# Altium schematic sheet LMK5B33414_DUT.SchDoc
size C; Date: Not shown in title block; ApprovedBy: Not shown in title block; CheckedBy: Not shown in title block; Author: Not shown in title block; CompanyName: Not shown in title block; Engineer: Not shown in title block; Organization: Not shown in title block; Address1: Not shown in title block; Address2: Not shown in title block; Address3: Not shown in title block; Address4: Not shown in title block; DocumentNumber: 2; Revision: Use project parameter SCH_Rev; SheetNumber: 2; SheetTotal: 3; PageSetup: Record=PageOptions¦CenterHorizontal=True¦CenterVertical=True¦PrintScale=1.00¦XCorrection=1.00¦YCorrection=1.00¦PrintKind=0¦BorderSize=5000000¦LeftOffset=0¦BottomOffset=0¦Orientation=2¦PaperLength=1000¦PaperWidth=1000¦Scale=100¦PaperSource=15¦PrintQuality=600¦MediaType=1¦DitherType=10¦PaperKind=Letter¦PrintScaleMode=1
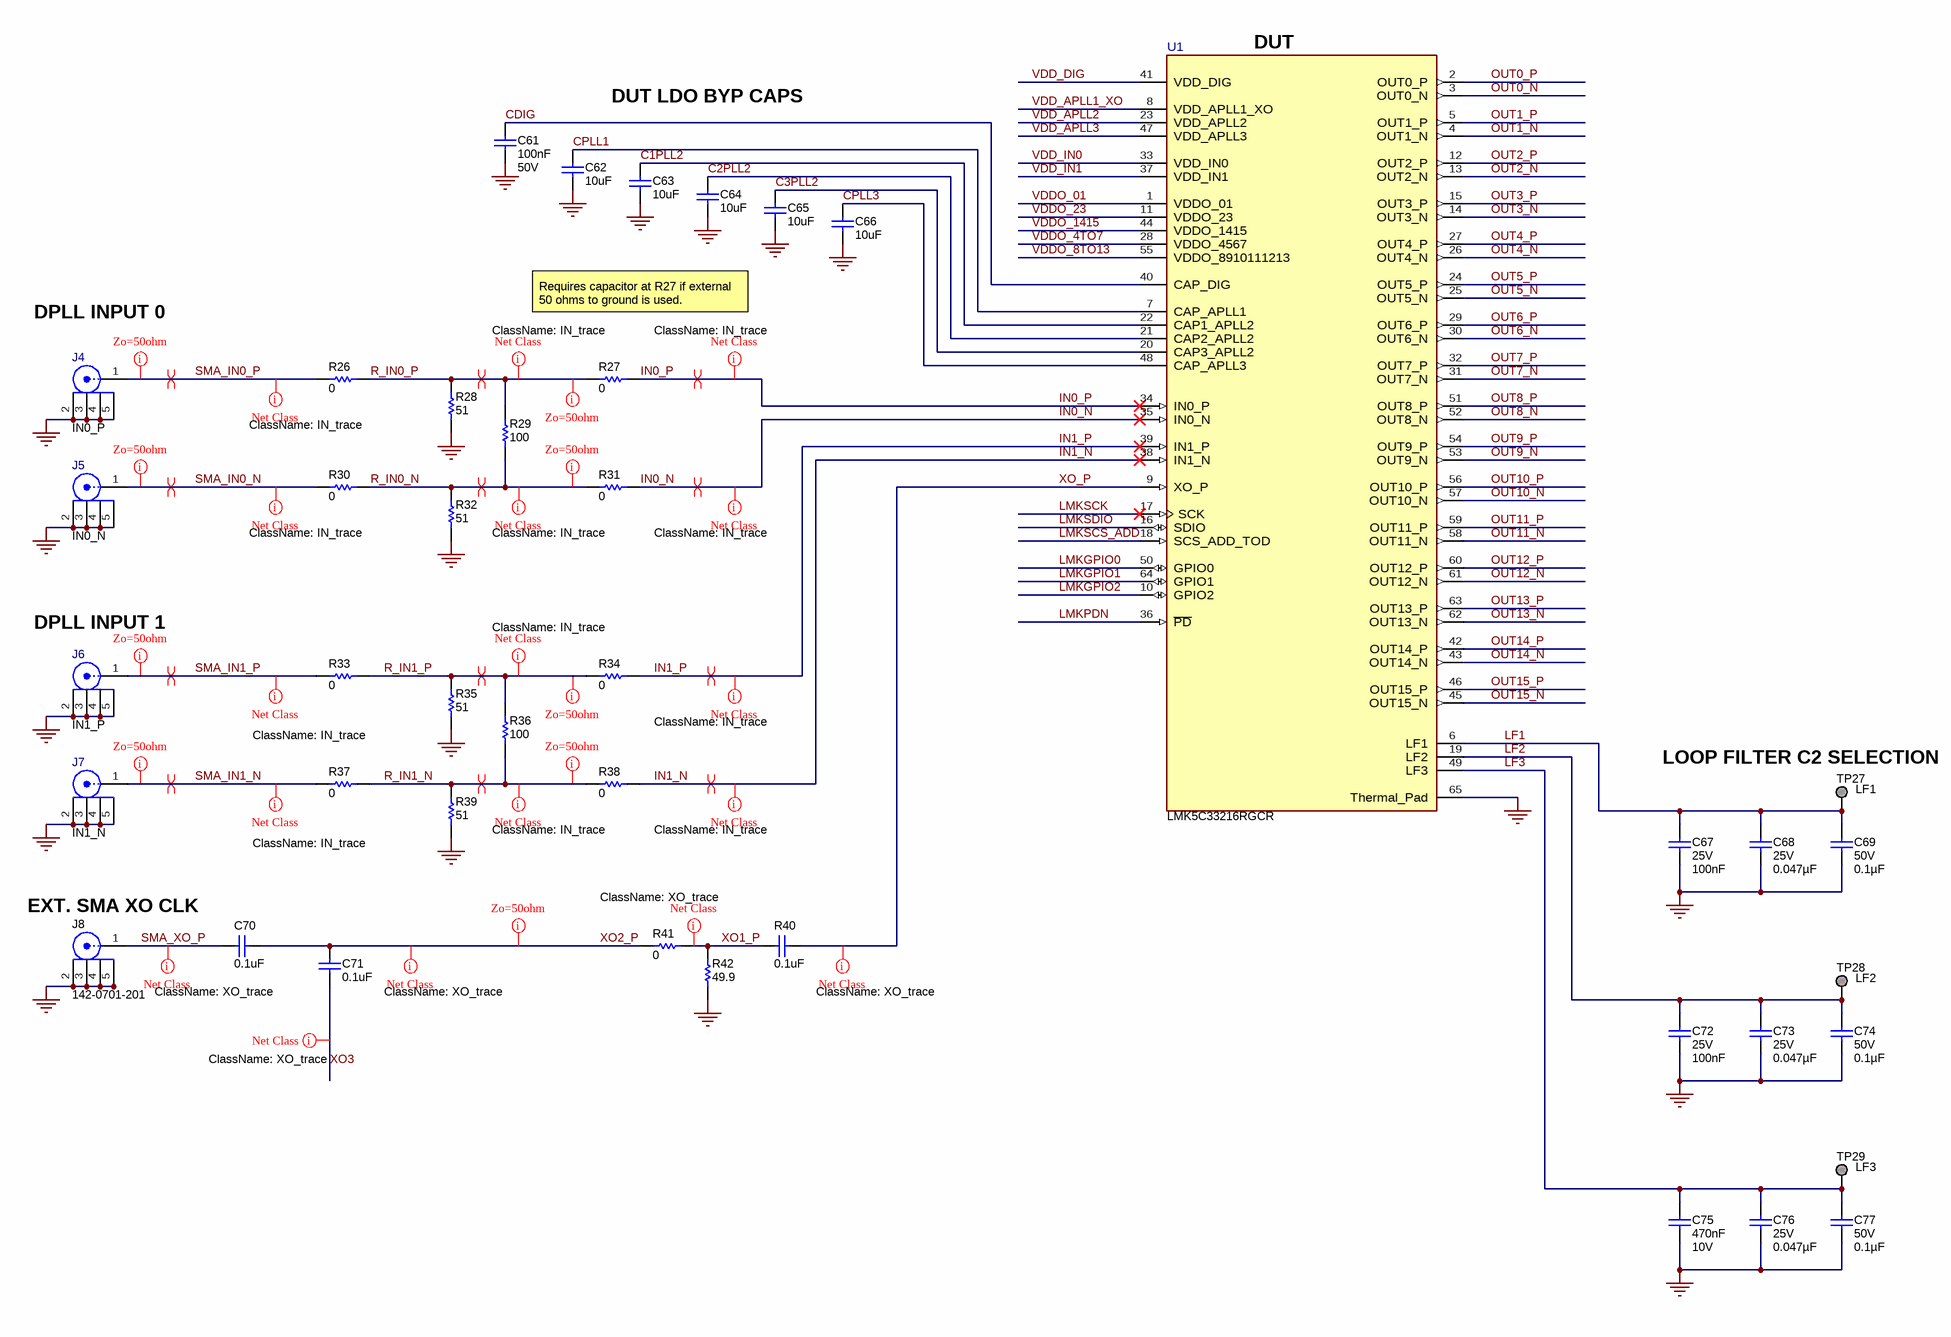
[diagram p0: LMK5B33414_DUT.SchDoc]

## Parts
C61  Cap_F: 100nF  VDC_V: 50V  [0603L]  (hidden comment: C1608X7R1H104K080AA)
C62  ValueDisplayed: 10uF  [0603L]  (hidden comment: Capacitor)
C63  ValueDisplayed: 10uF  [0603L]  (hidden comment: Capacitor)
C64  ValueDisplayed: 10uF  [0603L]  (hidden comment: Capacitor)
C65  ValueDisplayed: 10uF  [0603L]  (hidden comment: Capacitor)
C66  ValueDisplayed: 10uF  [0603L]  (hidden comment: Capacitor)
C67  VDC_V: 25V  Cap_F: 100nF  [0603]  (hidden comment: C0603C104J3RACTU)
C68  VDC_V: 25V  ValueDisplayed: 0.047µF  [0805_150]  (hidden comment: C0805C473J3GACTU)
C69  VDC_V: 50V  ValueDisplayed: 0.1µF  [1210_280]  (hidden comment: C3225C0G1H104J250AA)
C70  ValueDisplayed: 0.1uF  [0603S]  (hidden comment: C0603C104J3RACTU)
C71  ValueDisplayed: 0.1uF  [0603S]  (hidden comment: C0603C104J3RACTU)
C72  VDC_V: 25V  Cap_F: 100nF  [0603]  (hidden comment: C0603C104J3RACTU)
C73  VDC_V: 25V  ValueDisplayed: 0.047µF  [0805_150]  (hidden comment: Capacitor)
C74  VDC_V: 50V  ValueDisplayed: 0.1µF  [1210_280]  (hidden comment: C3225C0G1H104J250AA)
C75  Cap_F: 470nF  VDC_V: 10V  [0603]  (hidden comment: GRM188R71A474KA61D)
C76  VDC_V: 25V  ValueDisplayed: 0.047µF  [0805_150]  (hidden comment: Capacitor)
C77  VDC_V: 50V  ValueDisplayed: 0.1µF  [1210_280]  (hidden comment: C3225C0G1H104J250AA)
J4  IN0_P  [FP-CON-SMA-EDGE-S_CONN_JACK-MFG]
J5  IN0_N  [FP-CON-SMA-EDGE-S_CONN_JACK-MFG]
J6  IN1_P  [FP-CON-SMA-EDGE-S_CONN_JACK-MFG]
J7  IN1_N  [FP-CON-SMA-EDGE-S_CONN_JACK-MFG]
J8  142-0701-201  [Johnson_142-0701-20x]
R26  ValueDisplayed: 0  [0402L]  (hidden comment: CRCW04020000Z0EDHP)
R27  ValueDisplayed: 0  [0402L]  (hidden comment: CRCW04020000Z0EDHP)
R28  ValueDisplayed: 51  [0402S]  (hidden comment: RC0402JR-0751RL)
R29  ValueDisplayed: 100  [0603S]  (hidden comment: CRCW0603100RFKEA)
R30  ValueDisplayed: 0  [0402L]  (hidden comment: CRCW04020000Z0EDHP)
R31  ValueDisplayed: 0  [0402L]  (hidden comment: CRCW04020000Z0EDHP)
R32  ValueDisplayed: 51  [0402S]  (hidden comment: RC0402JR-0751RL)
R33  ValueDisplayed: 0  [0402L]  (hidden comment: CRCW04020000Z0EDHP)
R34  ValueDisplayed: 0  [0402L]  (hidden comment: CRCW04020000Z0EDHP)
R35  ValueDisplayed: 51  [0402S]  (hidden comment: RC0402JR-0751RL)
R36  ValueDisplayed: 100  [0603S]  (hidden comment: CRCW0603100RFKEA)
R37  ValueDisplayed: 0  [0402L]  (hidden comment: CRCW04020000Z0EDHP)
R38  ValueDisplayed: 0  [0402L]  (hidden comment: CRCW04020000Z0EDHP)
R39  ValueDisplayed: 51  [0402S]  (hidden comment: RC0402JR-0751RL)
R40  ValueDisplayed: 0.1uF  [0603S]  (hidden comment: Capacitor)
R41  value 0  [0603S]  (hidden comment: Resistor)
R42  ValueDisplayed: 49.9  [0603S]  (hidden comment: Resistor)
TP27  LF1  [TP_SM_1MM]  (no BOM)
TP28  LF2  [TP_SM_1MM]  (no BOM)
TP29  LF3  [TP_SM_1MM]  (no BOM)
U1  PartNumber: LMK5C33216RGCR  [RGC0064E-MFG]  (hidden comment: LMK05828V3RGCR)

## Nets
GND: C61.2 C62.2 C63.2 C64.2 C65.2 C66.2 C67.2 C68.1 C69.2 C72.2 C73.1 C74.2 C75.2 C76.1 C77.2 J4.2 J4.3 J4.4 J4.5 J5.2 J5.3 J5.4 J5.5 J6.2 J6.3 J6.4 J6.5 J7.2 J7.3 J7.4 J7.5 J8.2 J8.3 J8.4 J8.5 R28.1 R32.1 R35.1 R39.1 R42.1 U1.65(Thermal_Pad)
C1PLL2: C63.1 U1.22(CAP1_APLL2)
C2PLL2: C64.1 U1.21(CAP2_APLL2)
C3PLL2: C65.1 U1.20(CAP3_APLL2)
CDIG: C61.1 U1.40(CAP_DIG)
CPLL1: C62.1 U1.7(CAP_APLL1)
CPLL3: C66.1 U1.48(CAP_APLL3)
IN0_N: R31.2 U1.35(IN0_N)
IN0_P: R27.2 U1.34(IN0_P)
IN1_N: R38.2 U1.38(IN1_N)
IN1_P: R34.2 U1.39(IN1_P)
LF1: C67.1 C68.2 C69.1 TP27.1 U1.6(LF1)
LF2: C72.1 C73.2 C74.1 TP28.1 U1.19(LF2)
LF3: C75.1 C76.2 C77.1 TP29.1 U1.49(LF3)
LMKGPIO0: U1.50(GPIO0)
LMKGPIO1: U1.64(GPIO1)
LMKGPIO2: U1.10(GPIO2)
LMKPDN: U1.36(~{PD})
LMKSCK: U1.17(SCK)
LMKSCS_ADD: U1.18(SCS_ADD_TOD)
LMKSDIO: U1.16(SDIO)
OUT0_N: U1.3(OUT0_N)
OUT0_P: U1.2(OUT0_P)
OUT1_N: U1.4(OUT1_N)
OUT1_P: U1.5(OUT1_P)
OUT2_N: U1.13(OUT2_N)
OUT2_P: U1.12(OUT2_P)
OUT3_N: U1.14(OUT3_N)
OUT3_P: U1.15(OUT3_P)
OUT4_N: U1.26(OUT4_N)
OUT4_P: U1.27(OUT4_P)
OUT5_N: U1.25(OUT5_N)
OUT5_P: U1.24(OUT5_P)
OUT6_N: U1.30(OUT6_N)
OUT6_P: U1.29(OUT6_P)
OUT7_N: U1.31(OUT7_N)
OUT7_P: U1.32(OUT7_P)
OUT8_N: U1.52(OUT8_N)
OUT8_P: U1.51(OUT8_P)
OUT9_N: U1.53(OUT9_N)
OUT9_P: U1.54(OUT9_P)
OUT10_N: U1.57(OUT10_N)
OUT10_P: U1.56(OUT10_P)
OUT11_N: U1.58(OUT11_N)
OUT11_P: U1.59(OUT11_P)
OUT12_N: U1.61(OUT12_N)
OUT12_P: U1.60(OUT12_P)
OUT13_N: U1.62(OUT13_N)
OUT13_P: U1.63(OUT13_P)
OUT14_N: U1.43(OUT14_N)
OUT14_P: U1.42(OUT14_P)
OUT15_N: U1.45(OUT15_N)
OUT15_P: U1.46(OUT15_P)
R_IN0_N: R29.1 R30.2 R31.1 R32.2
R_IN0_P: R26.2 R27.1 R28.2 R29.2
R_IN1_N: R36.1 R37.2 R38.1 R39.2
R_IN1_P: R33.2 R34.1 R35.2 R36.2
SMA_IN0_N: J5.1 R30.1
SMA_IN0_P: J4.1 R26.1
SMA_IN1_N: J7.1 R37.1
SMA_IN1_P: J6.1 R33.1
SMA_XO_P: C70.1 J8.1
VDD_APLL1_XO: U1.8(VDD_APLL1_XO)
VDD_APLL2: U1.23(VDD_APLL2)
VDD_APLL3: U1.47(VDD_APLL3)
VDD_DIG: U1.41(VDD_DIG)
VDD_IN0: U1.33(VDD_IN0)
VDD_IN1: U1.37(VDD_IN1)
VDDO_01: U1.1(VDDO_01)
VDDO_4TO7: U1.28(VDDO_4567)
VDDO_8TO13: U1.55(VDDO_8910111213)
VDDO_23: U1.11(VDDO_23)
VDDO_1415: U1.44(VDDO_1415)
XO1_P: R40.1 R41.2 R42.2
XO2_P: C70.2 C71.1 R41.1
XO3: C71.2
XO_P: R40.2 U1.9(XO_P)

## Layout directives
rule Impedance Constraint [Min = 45.00    Max = 55.00    ]: R_IN0_N, R_IN0_P, R_IN1_N, R_IN1_P, SMA_IN0_N, SMA_IN0_P, SMA_IN1_N, SMA_IN1_P, XO2_P
differential pair: IN0_N, IN0_P, IN1_N, IN1_P, R_IN0_N, R_IN0_P, R_IN1_N, R_IN1_P, SMA_IN0_N, SMA_IN0_P, SMA_IN1_N, SMA_IN1_P
net class XO_trace: SMA_XO_P, XO1_P, XO2_P, XO3, XO_P
net class IN_trace: IN0_N, IN0_P, IN1_N, IN1_P, R_IN0_N, R_IN0_P, R_IN1_N, R_IN1_P, SMA_IN0_N, SMA_IN0_P, SMA_IN1_N, SMA_IN1_P

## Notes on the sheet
- (near U1) DUT
- DUT LDO BYP CAPS
- DPLL INPUT 0
- Requires capacitor at R27 if external 50 ohms to ground is used.
- (near J6) DPLL INPUT 1
- (near TP27) LOOP FILTER C2 SELECTION
- (near J8) EXT. SMA XO CLK

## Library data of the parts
C61 = CMP-0007044-5: CAP, CERM, 0.1 uF, 50 V, +/- 10%, X7R, 0603; Manufacturer: TDK; Polarized: N; Value: 0.1uF; U/M: EA; ESR_ohm: 0.0296; Value1: 0.0296 ohm; IRMS_A: 9.7199dA; TaMin_C: -55°C; TaMax_C: 125°C; Cap_Case: 0603; SizeArea_mm2: 1.28; SizeAreaWB_mm2: 4.68; SizeX_mm: 1.6; SizeY_mm: 0.8; SizeZ_mm: 1; AEC Category: Q200
C62-C66 = CMP-0007003-5: CAP, CERM, 10 uF, 10 V, +/- 20%, X5R, 0603; PartNumber: C1608X5R1A106M080AC; Manufacturer: TDK; Polarized: N; Value: 10uF; U/M: EA; Cap_F: 10µF; ESR_ohm: 7.8m; Value1: 0.0078 ohm; VDC_V: 10V; IRMS_A: 1.85A; TaMin_C: -55°C; TaMax_C: 85°C; Cap_Case: 0603; SizeArea_mm2: 1.28; SizeAreaWB_mm2: 4.68; SizeX_mm: 1.6; SizeY_mm: 0.8; SizeZ_mm: 1; AEC Category: Q200
C67 C72 = CMP-0006856-6: CAP, CERM, 0.1 uF, 25 V, +/- 5%, X7R, 0603; Manufacturer: Kemet; Polarized: N; TaMax_C: 125°C; TaMin_C: -55°C; Value: 0.1uF; Value1: Unknown; U/M: EA; AEC Category: Q200; SizeArea_mm2: 1.28; SizeAreaWB_mm2: 4.68; SizeX_mm: 1.6; SizeY_mm: 0.8; SizeZ_mm: 1
C68 = CMP-0078743-1: CAP, CERM, 0.047 µF, 25 V,+/- 5%, C0G/NP0, AEC-Q200 Grade 1, 0805; Manufacturer: Kemet; Polarized: N; TaMax_C: 125°C; TaMin_C: -55°C; Cap_F: 47nF; Value: 0.047uF; U/M: EA; SizeArea_mm2: 2.5; SizeAreaWB_mm2: 6.75; SizeX_mm: 2; SizeY_mm: 1.25; SizeZ_mm: 1.5; AEC Category: Q200; AEC Qualified: Y; AEC Grade: 1; Green_REACh: Incomplete; Green_Lifecycle: Not Set
C69 C74 C77 = CMP-0081101-1: CAP, CERM, 0.1 µF, 50 V,+/- 5%, C0G/NP0, 1210; Manufacturer: TDK; TaMin_C: -55°C; Polarized: N; SizeAreaWB_mm2: 14.7; U/M: EA; Value: 0.1uF; TaMax_C: 125°C; SizeZ_mm: 2.8; SizeX_mm: 3.2; SizeY_mm: 2.5; Cap_Case: 1210; SizeArea_mm2: 8; Cap_F: 100nF; AEC Category: Q200; Green_Lifecycle: Active; Green_REACh: Incomplete
C70 C71 = CMP-0006856-6: CAP, CERM, 0.1 uF, 25 V, +/- 5%, X7R, 0603; Manufacturer: Kemet; TaMin_C: -55°C; Polarized: N; SizeAreaWB_mm2: 4.68; Value1: Unknown; U/M: EA; Value: 0.1uF; TaMax_C: 125°C; SizeZ_mm: 1; SizeX_mm: 1.6; SizeY_mm: 0.8; Cap_Case: 0603; Value2: 25V; SizeArea_mm2: 1.28; Cap_F: 100nF; AEC Category: Q200
C73 C76 = CMP-0078743-1: CAP, CERM, 0.047 µF, 25 V,+/- 5%, C0G/NP0, AEC-Q200 Grade 1, 0805; Manufacturer: Kemet; PartNumber: C0805C473J3GACTU; Polarized: N; TaMax_C: 125°C; TaMin_C: -55°C; Cap_F: 47nF; Value: 0.047uF; U/M: EA; SizeArea_mm2: 2.5; SizeAreaWB_mm2: 6.75; SizeX_mm: 2; SizeY_mm: 1.25; SizeZ_mm: 1.5; AEC Category: Q200; AEC Qualified: Y; AEC Grade: 1; Green_REACh: Incomplete; Green_Lifecycle: Not Set
C75 = CMP-0007373-4: CAP, CERM, 0.47 uF, 10 V, +/- 10%, X7R, 0603; Manufacturer: MuRata; Polarized: N; Value: 0.47uF; U/M: EA; Value1: Unknown; TaMin_C: -55°C; TaMax_C: 125°C; SizeArea_mm2: 1.28; SizeAreaWB_mm2: 4.68; SizeX_mm: 1.6; SizeY_mm: 0.8; SizeZ_mm: 1; AEC Category: Q200
J4-J7 = CMP-0088000-4: CONN SMA JACK STR EDGE MNT; Manufacturer: RF Solutions Ltd.; PartNumber: CON-SMA-EDGE-S; ContactFinish: Gold; Shrouded: true
J8 = CMP-0055819-1: Connector, SMA, TH; Manufacturer: Cinch Connectivity; CNHeader: FALSE; CT: TRUE; Green_Lifecycle: Not Set; Green_REACh: Incomplete
R26 R30 R31 R33 R34 R37 R38 = CMP-0081856-1: RES, 0, 0%, 0.2 W, AEC-Q200 Grade 0, 0402; Manufacturer: Vishay-Dale; VDC_V: 50V; Power_W: 200mW; Value: 0; Value2: 0.2W; AEC Category: Q200; AEC Qualified: Y; SizeArea_mm2: 0.5; SizeX_mm: 1; SizeZ_mm: 0.6; SizeAreaWB_mm2: 3
R27 = CMP-0081856-1: RES, 0, 0%, 0.2 W, AEC-Q200 Grade 0, 0402; Manufacturer: Vishay-Dale; CompType: Resistor; VDC_V: 50V; Power_W: 200mW; Value: 0; Value2: 0.2W; AEC Category: Q200; AEC Qualified: Y; SizeArea_mm2: 0.5; SizeX_mm: 1; SizeZ_mm: 0.6; SizeAreaWB_mm2: 3
R28 R32 R35 R39 = CMP-0027006-2: RES, 51, 5%, 0.0625 W, 0402; Manufacturer: Yageo America; Value: 51; Value_Code: 51R0; Power_W: 62.5mW; VDC_V: 50V; TempCo: 100 ppm/C; EIA_Code: E24; AEC Category: Q200; AEC Qualified: N; SizeArea_mm2: 0.5; SizeX_mm: 1; SizeZ_mm: 0.6; U/M: EA
R29 R36 = CMP-0021991-4: RES, 100, 1%, 0.1 W, AEC-Q200 Grade 0, 0603; Manufacturer: Vishay-Dale; Value: 100; Value_Code: 100R; Power_W: 100mW; Value2: 0.1W; VDC_V: 75V; TempCo: 100 ppm/C; EIA_Code: E96; AEC Category: Q200; AEC Qualified: Y; AEC Grade: 0; SizeArea_mm2: 1.28; SizeX_mm: 1.6; SizeY_mm: 0.8; SizeZ_mm: 1
R40 = CMP-0006856-6: CAP, CERM, 0.1 uF, 25 V, +/- 5%, X7R, 0603; Manufacturer: Kemet; PartNumber: C0603C104J3RACTU; VDC_V: 25V; Value: 0.1uF; Value1: Unknown; U/M: EA; Polarized: N; Cap_F: 100nF; TaMin_C: -55°C; TaMax_C: 125°C; Cap_Case: 0603; SizeArea_mm2: 1.28; SizeAreaWB_mm2: 4.68; SizeX_mm: 1.6; SizeY_mm: 0.8; SizeZ_mm: 1; AEC Category: Q200
R41 = CMP-0025697-4: RES, 0, 5%, 0.1 W, AEC-Q200 Grade 0, 0603; Manufacturer: Vishay-Dale; PartNumber: CRCW06030000Z0EA; VDC_V: 75V; Power_W: 100mW; Value_Code: 0000; Value2: 0.1W; EIA_Code: E24; TempCo: 200 ppm/C; AEC Category: Q200; AEC Qualified: Y; SizeArea_mm2: 1.28; SizeX_mm: 1.6; SizeY_mm: 0.8; SizeZ_mm: 1
R42 = CMP-0022448-4: RES, 49.9, 1%, 0.1 W, AEC-Q200 Grade 0, 0603; PartNumber: CRCW060349R9FKEA; Manufacturer: Vishay-Dale; Value: 49.9; Value_Code: 49R9; Power_W: 100mW; Value2: 0.1W; VDC_V: 75V; TempCo: 100 ppm/C; EIA_Code: E96; AEC Category: Q200; AEC Qualified: Y; AEC Grade: 0; SizeArea_mm2: 1.28; SizeX_mm: 1.6; SizeY_mm: 0.8; SizeZ_mm: 1
TP27-TP29 = CMP-0003825-1: 1mm Test Point, SMT; Manufacturer: Any
U1 = CMP-0088768-1: Ultra-Low Jitter Clock Synchronizer with JESD204B for Wireless Communications; Manufacturer: Texas Instruments; Max Supply Voltage: 3.465V; AEC Qualified: No; Interface: I2C,SPI; Number Of Outputs: 16; Standoff Height: 0mm; TJmax_C: +135°C; Max Frequency: 2.94912GHz; Min Supply Voltage: 3.135V; Pll: YES; SizeZ_mm: 1mm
